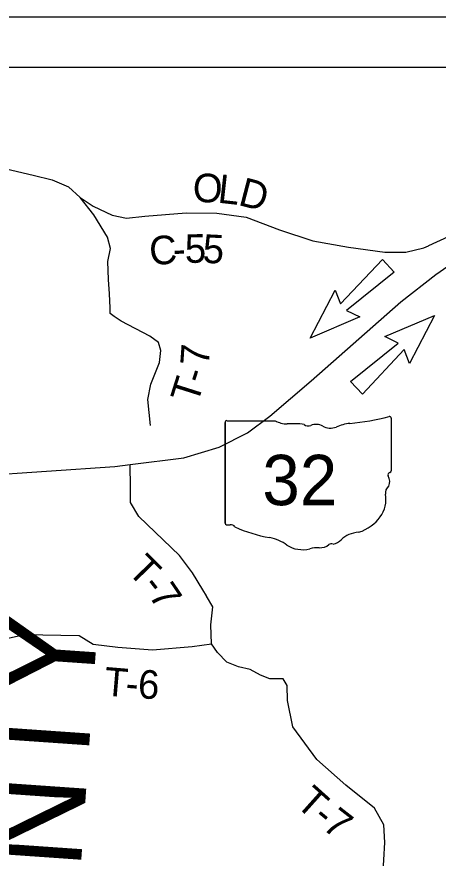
# Model space of a CAD drawing. Extents: x -15 to 405, y -40 to 87.
# Drawn here: x 27.6 to 28.436, y -28.766 to -27.096 of the extents above; entities that cross this region are included whole.
import ezdxf

# ---------------------------------------------------------------- set-up
doc = ezdxf.new("R2010")
doc.units = 0
for name, color, linetype in [('GM_P_State_Alignment', 7, 'Continuous'), ('GM_P_State_Location', 7, 'Continuous'), ('GM_X_Minor_Lake', 7, 'Continuous'), ('GM_X_Minor_River', 7, 'Continuous'), ('GM_X_State_Location', 7, 'Continuous'), ('GM_X_Township', 7, 'Continuous'), ('GM_X_Township_Subdivision', 7, 'Continuous'), ('GM_X_Township_Text', 7, 'Continuous')]:
    doc.layers.add(name, color=color, linetype=linetype)

msp = doc.modelspace()

# ---------------------------------------------------------------- linework, layer by layer
at = {"layer": 'GM_P_State_Location'}
for points in [[(27.8648, -27.9069), (27.8599, -27.8552), (27.8659, -27.8248), (27.8826, -27.7819), (27.8853, -27.758), (27.8807, -27.742), (27.8636, -27.7295), (27.807, -27.6999), (27.793, -27.6903), (27.7847, -27.6843), (27.785, -27.6733), (27.7838, -27.6452), (27.7815, -27.6171), (27.78, -27.5814), (27.7856, -27.5552), (27.7799, -27.5332), (27.7522, -27.4884), (27.7252, -27.4543)], [(27.9762, -28.2454), (27.976, -28.245), (27.9691, -28.233), (27.9482, -28.1992), (27.9227, -28.1647), (27.8418, -28.0877), (27.8254, -28.0599), (27.825, -28.0299), (27.8248, -27.9846)], [(28.3219, -28.8724), (28.3302, -28.7349), (28.3283, -28.7), (28.3093, -28.6666), (28.2527, -28.621), (28.1953, -28.5702), (28.1474, -28.5049), (28.1371, -28.4528), (28.1363, -28.4232), (28.128, -28.4096), (28.1124, -28.4096), (28.1018, -28.4096), (28.0835, -28.4024), (28.063, -28.3914), (28.0398, -28.3857), (28.0167, -28.377), (27.9977, -28.3576), (27.9863, -28.3405), (27.9847, -28.3029), (27.9889, -28.2672), (27.9762, -28.2454)], [(27.4986, -28.3432), (27.5435, -28.3374), (27.6152, -28.3221), (27.7235, -28.324), (27.7512, -28.341), (27.7998, -28.3471), (27.8689, -28.3524), (27.9475, -28.3459), (27.9863, -28.3405)]]:
    msp.add_lwpolyline(points, dxfattribs=at)
at = {"layer": 'GM_X_State_Location'}
for p, q in [((28.2423, -27.6655), (28.3252, -27.5772)), ((28.3252, -27.5772), (28.3486, -27.6024)), ((28.3486, -27.6024), (28.2541, -27.6783)), ((28.1821, -27.7332), (28.2315, -27.6383)), ((28.2315, -27.6383), (28.2423, -27.6655)), ((28.2541, -27.6783), (28.2805, -27.6913)), ((28.2805, -27.6913), (28.1821, -27.7332)), ((28.3302, -27.7304), (28.4286, -27.6885)), ((28.4286, -27.6885), (28.3793, -27.7835)), ((28.2621, -27.8194), (28.3566, -27.7436)), ((28.3566, -27.7436), (28.3302, -27.7304)), ((28.3684, -27.7563), (28.2856, -27.8447)), ((28.3793, -27.7835), (28.3684, -27.7563)), ((28.2856, -27.8447), (28.2621, -27.8194))]:
    msp.add_line(p, q, dxfattribs=at)
msp.add_lwpolyline([(27.5221, -28.0069), (27.794, -27.9884), (27.8248, -27.9846), (27.9313, -27.9711), (28.0014, -27.9502), (28.0572, -27.9216), (28.1015, -27.8881), (28.1837, -27.8185), (28.3618, -27.6615), (28.4315, -27.6071), (28.5024, -27.5572), (28.767, -27.3945)], dxfattribs=at)
at = {"layer": 'GM_X_Township'}
for p, q in [((23.0652, -27.0955), (30.0652, -27.0955)), ((23.1652, -27.1955), (29.9652, -27.1955))]:
    msp.add_line(p, q, dxfattribs=at)
at = {"layer": 'GM_X_Township_Subdivision'}
for p, q in [((28.3426, -27.8924), (28.3426, -27.997)), ((28.013, -27.9008), (28.013, -28.1009)), ((28.013, -28.1009), (28.013, -27.9008)), ((28.013, -28.1009), (28.013, -27.9008)), ((28.0162, -27.8973), (28.1127, -27.8973)), ((28.3425, -27.997), (28.3426, -27.997))]:
    msp.add_line(p, q, dxfattribs=at)
for centre, major_axis, start_param, end_param in [((28.2252, -27.6245), (0.3495, 0), 4.814394, 5.042369), ((28.3389, -27.8919), (0.00367, 0), 6.141152, 7.989035), ((28.0167, -27.9003), (0.00382, 0), 1.712693, 3.28349), ((28.1357, -27.8741), (0.037, 0), 4.042523, 4.731795), ((28.148, -28.0097), (0.133, 0), 1.404758, 1.657858), ((28.1782, -27.8993), (0.0107, 0), 3.836095, 5.185415), ((28.1939, -27.9224), (0.0222, 0), 0.950623, 2.079405), ((28.2225, -27.8907), (0.0267, 0), 4.081561, 5.145723), ((28.2697, -27.9584), (0.0703, 0), 1.699011, 2.107814), ((28.3417, -28.0047), (0.00568, 0), 1.883978, 3.671073), ((28.3056, -28.018), (0.0341, 0), 5.934695, 6.695948), ((28.3386, -27.9975), (0.00393, 0), 5.05454, 6.418171), ((28.3557, -28.0409), (0.0248, 0), 2.387724, 3.262537), ((28.2447, -28.0542), (0.0874, 0), 5.101752, 6.440018), ((28.0168, -28.1013), (0.00385, 0), 3.00124, 4.508301), ((28.0174, -28.0808), (0.0294, 0), 4.665946, 4.897461), ((28.0234, -28.1124), (0.0106, 0), 0.519207, 1.627899), ((28.1572, -27.9326), (0.2524, 0), 4.195997, 4.488961), ((28.082, -28.1908), (0.079, 0), 0.823519, 1.323587), ((28.2816, -28.1571), (0.0479, 0), 1.647645, 2.488434), ((28.1674, -28.1134), (0.0501, 0), 4.026481, 4.996735), ((28.2, -28.1284), (0.0267, 0), 4.691044, 5.507374), ((28.2241, -28.1478), (0.00752, 0), 1.147584, 2.315152), ((28.2209, -28.1203), (0.0282, 0), 4.937069, 5.64225), ((28.1963, -28.1826), (0.0412, 0), 1.495662, 1.94098)]:
    msp.add_ellipse(centre, major_axis=major_axis, ratio=0.8, start_param=start_param, end_param=end_param, dxfattribs=at)
at = {"layer": 'GM_X_Township_Text'}
for points in [[(28.4164, -27.5499), (28.4174, -27.5495), (28.5573, -27.4856), (28.7456, -27.3607), (28.8625, -27.2799)], [(27.567, -27.3948), (27.6319, -27.4097), (27.6698, -27.4189), (27.702, -27.4333), (27.7252, -27.4543), (27.751, -27.4717), (27.7886, -27.4895), (27.8171, -27.4952), (27.854, -27.4914), (27.9356, -27.4845), (27.9967, -27.4852), (28.0545, -27.4932), (28.1213, -27.5186), (28.187, -27.5402), (28.2577, -27.553), (28.3302, -27.5629), (28.372, -27.5629), (28.4073, -27.5541), (28.4164, -27.5499)]]:
    msp.add_lwpolyline(points, dxfattribs=at)

# ---------------------------------------------------------------- texts
at = {"layer": 'GM_P_State_Alignment'}
msp.add_text('MEIGS  COUNTY', height=0.189394, rotation=86.0177, dxfattribs=at).set_placement((27.6206, -30.3058))
at = {"layer": 'GM_X_Minor_Lake'}
for s, rotation, p in [('O', 358.2366, (27.9482, -27.4629)), ('L', 353.666, (27.997, -27.4643)), ('D', 345.4253, (28.0371, -27.4686)), ('5', 0.6922, (27.9334, -27.5841)), ('5', 357.194, (27.9675, -27.5837)), ('C', 4.1603, (27.8645, -27.5888)), ('-', 3.2959, (27.9108, -27.5854))]:
    msp.add_text(s, height=0.0568, rotation=rotation, dxfattribs=at).set_placement(p)
at = {"layer": 'GM_X_Minor_River'}
for s, rotation, p in [('7', 85.9944, (27.9805, -27.7895)), ('T', 72.4182, (27.9578, -27.8666)), ('-', 72.1575, (27.9706, -27.8262)), ('T', 314.8197, (27.8171, -28.1975)), ('-', 308.1502, (27.8459, -28.2264)), ('7', 304.1346, (27.8597, -28.2439)), ('T', 355.2203, (27.7714, -28.4428)), ('6', 357.0769, (27.839, -28.4483)), ('-', 355.4995, (27.8141, -28.4463)), ('T', 318.1668, (28.1507, -28.6602)), ('7', 322.061, (28.2035, -28.7061)), ('-', 320.2697, (28.1841, -28.69))]:
    msp.add_text(s, height=0.0568, rotation=rotation, dxfattribs=at).set_placement(p)
at = {"layer": 'GM_X_Township_Subdivision'}
msp.add_text('32', height=0.1, dxfattribs=at).set_placement((28.0869, -28.0651))

doc.saveas('drawing.dxf')
